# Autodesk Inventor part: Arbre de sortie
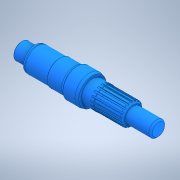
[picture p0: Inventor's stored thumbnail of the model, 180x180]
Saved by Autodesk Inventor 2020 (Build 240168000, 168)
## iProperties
Created: 2003-05
Part Number: Arbre de sortie
Material: Générique
Document SubType Name: Modeling
Designer: Bruno
Density: 1 g/cm^3
Appearance: Par défaut
Author: Bruno
Sending System: SolidWorks 2011
Last Author: frederic
Last Saved: 2012-02-20
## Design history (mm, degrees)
feature "Répétition circulaire1"
node "Solide1"
